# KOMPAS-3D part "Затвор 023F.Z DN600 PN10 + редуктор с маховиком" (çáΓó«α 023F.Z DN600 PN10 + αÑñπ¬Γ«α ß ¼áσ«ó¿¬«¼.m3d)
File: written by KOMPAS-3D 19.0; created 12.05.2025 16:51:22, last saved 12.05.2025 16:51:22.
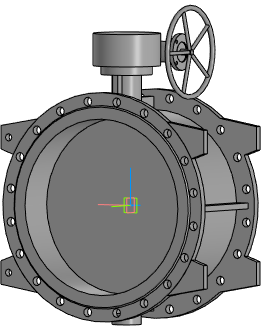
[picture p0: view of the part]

Document properties: Полное имя файла: Затвор 023F.Z DN600 PN10 + редуктор с маховиком.a3d

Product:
- Part/product: Затвор 023F.Z DN600 PN10 + редуктор с маховиком
    Масса: 389.004

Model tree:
1. Операция без истории:1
